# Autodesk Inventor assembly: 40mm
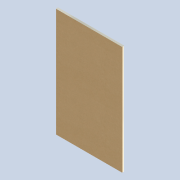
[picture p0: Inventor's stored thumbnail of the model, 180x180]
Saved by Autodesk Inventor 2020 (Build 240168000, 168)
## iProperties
Created: 2020-11
Part Number: 40mm
Document SubType Name: Assembly
Designer: Yolande
Author: Yolande
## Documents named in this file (2)
- D:\Drawing Division\3. Revit Family Files\2. Kraft\40mm.iam
- D:\Drawing Division\3. Revit Family Files\2. Kraft\Lambdaboard 40mm Kraft.ipt
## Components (1 placed, 1 different names)
1. Lambdaboard 40mm Kraft:1
